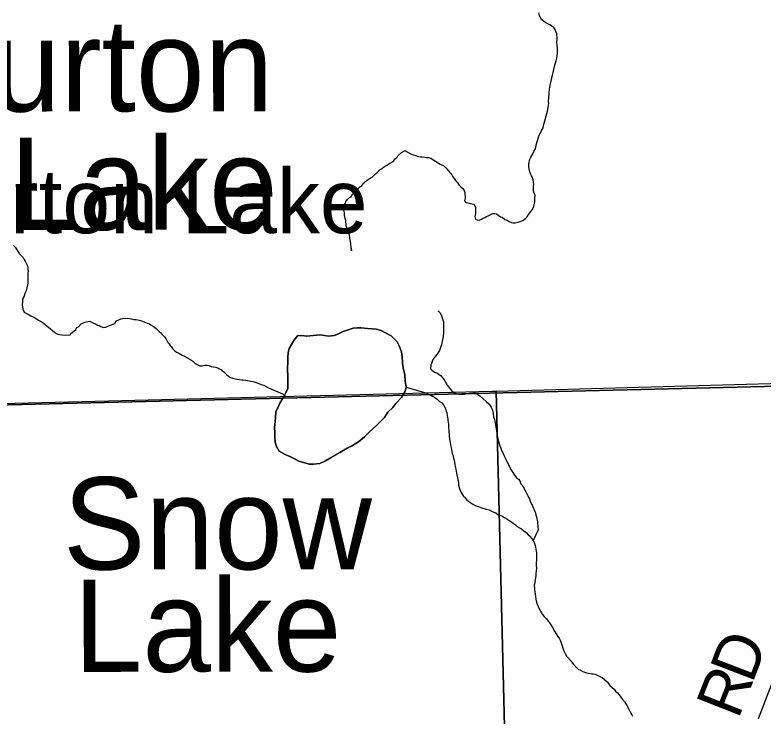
# Model space of a CAD drawing. Extents: x 10.6 to 44.6, y -2.6 to 23.4.
# Drawn here: x 15.619 to 16.54, y 20.49 to 21.353 of the extents above; entities that cross this region are included whole.
import ezdxf

# ---------------------------------------------------------------- set-up
doc = ezdxf.new("R2010")
doc.units = 0
for name, color, linetype in [('GM_X_County_Road', 7, 'Continuous'), ('GM_X_County_Road_Text', 7, 'Continuous'), ('GM_X_Minor_Lake', 7, 'Continuous'), ('GM_X_Minor_Lake_Text', 7, 'Continuous'), ('GM_X_Minor_River', 7, 'Continuous'), ('GM_X_Section', 7, 'Continuous'), ('GM_X_Township', 7, 'Continuous'), ('GM_X_Unincorporated_Text', 7, 'Continuous')]:
    doc.layers.add(name, color=color, linetype=linetype)

msp = doc.modelspace()

# ---------------------------------------------------------------- linework, layer by layer
at = {"layer": 'GM_X_County_Road'}
msp.add_lwpolyline([(16.56144, 20.55649), (16.53429, 20.48618)], dxfattribs=at)
at = {"layer": 'GM_X_Minor_Lake'}
for points in [[(15.94541, 20.87517), (15.95148, 20.88544), (15.95527, 20.89342), (15.95528, 20.90709), (15.9549, 20.91811), (15.95528, 20.9257), (15.95528, 20.9314), (15.95566, 20.93748), (15.9568, 20.94242), (15.96249, 20.9523), (15.96705, 20.958), (15.97236, 20.95839), (15.97843, 20.95763), (15.9864, 20.95841), (15.99437, 20.95955), (16.00044, 20.95842), (16.00575, 20.95767), (16.0122, 20.95843), (16.01751, 20.96072), (16.0232, 20.96338), (16.02813, 20.96529), (16.03572, 20.96758), (16.04066, 20.96796), (16.04559, 20.96797), (16.05318, 20.96722), (16.05887, 20.96684), (16.0638, 20.96647), (16.07025, 20.96458), (16.07556, 20.96193), (16.08239, 20.95814), (16.0896, 20.95055), (16.09225, 20.94562), (16.09529, 20.9384), (16.09605, 20.9327), (16.09642, 20.92435), (16.09718, 20.91865), (16.09908, 20.90992), (16.09983, 20.90232), (16.10097, 20.89473), (16.09983, 20.88979), (16.09528, 20.88219), (16.08807, 20.87496), (16.08427, 20.86964), (16.0782, 20.86394), (16.07403, 20.85747), (16.06454, 20.84797), (16.05505, 20.83884), (16.04974, 20.83352), (16.04215, 20.82743), (16.03342, 20.8221), (16.02811, 20.81982), (16.019, 20.81449), (16.00838, 20.8084), (16.00079, 20.80383), (15.99472, 20.80078), (15.98675, 20.80002), (15.98144, 20.80001), (15.97613, 20.80152), (15.96854, 20.80379), (15.96247, 20.80682), (15.95754, 20.80948), (15.95184, 20.81175), (15.94426, 20.81592), (15.94122, 20.82161), (15.9397, 20.82731), (15.93933, 20.83376), (15.93933, 20.83946), (15.93857, 20.84478), (15.94009, 20.85694), (15.94047, 20.86491), (15.94313, 20.87023), (15.94541, 20.87517)], [(16.09718, 20.91865), (16.09642, 20.92435), (16.09605, 20.9327), (16.09529, 20.9384), (16.09225, 20.94562), (16.0896, 20.95055), (16.08239, 20.95814), (16.07556, 20.96193), (16.07025, 20.96458), (16.0638, 20.96647), (16.05887, 20.96684), (16.05318, 20.96722), (16.04559, 20.96797), (16.04066, 20.96796), (16.03572, 20.96758), (16.02813, 20.96529), (16.0232, 20.96338), (16.01751, 20.96072), (16.0122, 20.95843), (16.00575, 20.95767), (16.00044, 20.95842), (15.99437, 20.95955), (15.9864, 20.95841), (15.97843, 20.95763), (15.97236, 20.95839), (15.96705, 20.958), (15.96249, 20.9523), (15.9568, 20.94242), (15.95566, 20.93748), (15.95528, 20.9314), (15.95528, 20.9257), (15.9549, 20.91811), (15.95528, 20.90709), (15.95527, 20.89342), (15.95148, 20.88544), (15.94541, 20.87517)], [(15.94541, 20.87517), (15.94313, 20.87023), (15.94047, 20.86491), (15.94009, 20.85694), (15.93857, 20.84478), (15.93933, 20.83946), (15.93933, 20.83376), (15.9397, 20.82731), (15.94122, 20.82161), (15.94426, 20.81592), (15.95184, 20.81175), (15.95754, 20.80948), (15.96247, 20.80682), (15.96854, 20.80379), (15.97613, 20.80152), (15.98144, 20.80001), (15.98675, 20.80002), (15.99472, 20.80078), (16.00079, 20.80383), (16.00838, 20.8084), (16.019, 20.81449), (16.02811, 20.81982), (16.03342, 20.8221), (16.04215, 20.82743), (16.04974, 20.83352), (16.05505, 20.83884), (16.06454, 20.84797), (16.07403, 20.85747), (16.0782, 20.86394), (16.08427, 20.86964), (16.08807, 20.87496), (16.09528, 20.88219), (16.09983, 20.88979), (16.10097, 20.89473), (16.09983, 20.90232), (16.09908, 20.90992), (16.09718, 20.91865)]]:
    msp.add_lwpolyline(points, dxfattribs=at)
at = {"layer": 'GM_X_Minor_River'}
for points in [[(16.21196, 21.10821), (16.21427, 21.10674), (16.21698, 21.1049), (16.21927, 21.10419), (16.22237, 21.1016), (16.22506, 21.10052), (16.22775, 21.09906), (16.23045, 21.0976), (16.23236, 21.09726), (16.23502, 21.09732), (16.23881, 21.09816), (16.24258, 21.09938), (16.24447, 21.10018), (16.24821, 21.10292), (16.25007, 21.10487), (16.25191, 21.10794), (16.2545, 21.11142), (16.25635, 21.11374), (16.25817, 21.11758), (16.25918, 21.12368), (16.25947, 21.12787), (16.25978, 21.13129), (16.25858, 21.13393), (16.25777, 21.13619), (16.25771, 21.13923), (16.25764, 21.14227), (16.25797, 21.14455), (16.25747, 21.15024), (16.25627, 21.15325), (16.25509, 21.15513), (16.25428, 21.15701), (16.25308, 21.16002), (16.25224, 21.16381), (16.25179, 21.16684), (16.25211, 21.16988), (16.25313, 21.1756), (16.25459, 21.1783), (16.25569, 21.18022), (16.25678, 21.18252), (16.25824, 21.18522), (16.26008, 21.1883), (16.26146, 21.19478), (16.26431, 21.20397), (16.26758, 21.21126), (16.26941, 21.21434), (16.27011, 21.21739), (16.27151, 21.22312), (16.27328, 21.22924), (16.27506, 21.23498), (16.27572, 21.23955), (16.27639, 21.24413), (16.27632, 21.24716), (16.27661, 21.25135), (16.27688, 21.25667), (16.27752, 21.26239), (16.27853, 21.26849), (16.27993, 21.27384), (16.28413, 21.29141), (16.28483, 21.29409), (16.28553, 21.29676), (16.28622, 21.30019), (16.28691, 21.30325), (16.28724, 21.30554), (16.28719, 21.3082), (16.28708, 21.31313), (16.28656, 21.31996), (16.28685, 21.32377), (16.28681, 21.32605), (16.28638, 21.32832), (16.28634, 21.33021), (16.28514, 21.33285), (16.28432, 21.33549), (16.28276, 21.33736), (16.28004, 21.33995), (16.27773, 21.34142), (16.27542, 21.34252), (16.27274, 21.3436), (16.27003, 21.34582), (16.2677, 21.34767), (16.26574, 21.35066), (16.26493, 21.35293), (16.2641, 21.35595)], [(16.03338, 21.06291), (16.03331, 21.06595), (16.03338, 21.06291), (16.03331, 21.06595), (16.0328, 21.07202), (16.03195, 21.07618), (16.03152, 21.07883), (16.03106, 21.08224), (16.03025, 21.0845), (16.02903, 21.08827), (16.02782, 21.09129), (16.02702, 21.09355), (16.02649, 21.10038), (16.02568, 21.10264), (16.02484, 21.10642), (16.02477, 21.10946), (16.02435, 21.11135), (16.02353, 21.11437), (16.02386, 21.11666), (16.02457, 21.11895), (16.02603, 21.12165), (16.02676, 21.12356), (16.02898, 21.12627), (16.03121, 21.1286), (16.03309, 21.12978), (16.03493, 21.13248), (16.03679, 21.13442), (16.03866, 21.13636), (16.04126, 21.13908), (16.04349, 21.1414), (16.04611, 21.14336), (16.04872, 21.14608), (16.05282, 21.14997), (16.05657, 21.15233), (16.05883, 21.15352), (16.0633, 21.1578), (16.06517, 21.15936), (16.06703, 21.1613), (16.0689, 21.16286), (16.07115, 21.16443), (16.07302, 21.16599), (16.07527, 21.16756), (16.07715, 21.16835), (16.08053, 21.17033), (16.08466, 21.17308), (16.08763, 21.17656), (16.08988, 21.17813), (16.0906, 21.18005), (16.09508, 21.18395), (16.09959, 21.18632), (16.10191, 21.18485), (16.10499, 21.18302), (16.10729, 21.18193), (16.10959, 21.18122), (16.11151, 21.1805), (16.11457, 21.17943), (16.11839, 21.17875), (16.12068, 21.17842), (16.12373, 21.17811), (16.12602, 21.17778), (16.1283, 21.17783), (16.13136, 21.17713), (16.14293, 21.16979), (16.14716, 21.1676), (16.14988, 21.165), (16.15262, 21.16164), (16.15573, 21.15829), (16.15691, 21.15641), (16.15848, 21.15417), (16.16005, 21.15192), (16.16163, 21.1493), (16.16357, 21.14744), (16.16593, 21.14369), (16.16826, 21.14184), (16.17059, 21.13961), (16.17216, 21.13699), (16.17297, 21.13472), (16.17351, 21.12752), (16.17281, 21.12446), (16.17438, 21.12221), (16.17667, 21.12189), (16.17973, 21.12119), (16.18164, 21.12085), (16.18432, 21.12015), (16.1855, 21.11828), (16.18631, 21.11602), (16.18635, 21.11412), (16.18609, 21.10841), (16.1854, 21.10498), (16.18623, 21.10195), (16.18815, 21.10086), (16.19082, 21.10053), (16.19271, 21.10134), (16.19496, 21.10252), (16.1976, 21.10372), (16.19985, 21.10529), (16.20174, 21.10609), (16.20513, 21.10769), (16.20776, 21.10888), (16.21004, 21.10893), (16.21196, 21.10821)], [(15.61745, 21.06943), (15.61941, 21.0672), (15.62452, 21.05933), (15.62724, 21.05673), (15.62919, 21.05449), (15.63038, 21.05224), (15.63156, 21.04998), (15.63315, 21.04698), (15.63435, 21.04434), (15.63478, 21.04207), (15.63483, 21.03979), (15.63525, 21.0379), (15.63492, 21.03524), (15.63498, 21.03258), (15.63505, 21.02916), (15.6351, 21.02688), (15.63476, 21.02497)], [(15.63476, 21.02497), (15.6348, 21.02307), (15.63447, 21.02078), (15.63378, 21.01735), (15.63273, 21.01353), (15.63127, 21.01046), (15.63057, 21.0074), (15.62947, 21.00548), (15.62838, 21.00317), (15.62845, 21.00013), (15.62815, 20.99633), (15.62821, 20.99329), (15.62905, 20.98951), (15.63062, 20.98726), (15.63332, 20.9858), (15.6364, 20.98397), (15.6387, 20.98288), (15.6414, 20.98142), (15.64447, 20.97997), (15.64795, 20.97738), (15.65257, 20.97482), (15.65683, 20.97149), (15.66031, 20.96891), (15.66728, 20.96298), (15.66921, 20.9615), (15.67191, 20.96004), (15.6742, 20.95971), (15.67687, 20.95939), (15.68182, 20.95912), (15.68562, 20.9592), (15.68752, 20.95924), (15.68786, 20.96115), (15.69161, 20.96389), (15.69385, 20.96584), (15.69531, 20.96853), (15.6972, 20.96933), (15.70055, 20.97283), (15.70243, 20.97363), (15.70696, 20.97525), (15.71113, 20.9761), (15.71574, 20.97392), (15.71842, 20.97284), (15.72074, 20.97137), (15.72266, 20.97065), (15.72496, 20.96956), (15.72803, 20.96849), (15.73106, 20.96893), (15.73332, 20.97012), (15.74011, 20.97255), (15.74237, 20.97374), (15.74346, 20.97604), (15.74948, 20.97921), (15.75213, 20.97965), (15.75708, 20.97976), (15.76013, 20.97945), (15.7628, 20.97912), (15.76548, 20.97842), (15.76852, 20.97811), (15.77196, 20.97742), (15.77502, 20.97673), (15.7781, 20.97527), (15.78193, 20.97384), (15.78462, 20.97276), (15.78654, 20.97166), (15.78924, 20.9702), (15.7931, 20.96724), (15.79466, 20.96538), (15.79661, 20.96352), (15.79893, 20.96167), (15.80049, 20.9598), (15.80322, 20.95682), (15.80478, 20.95496), (15.80598, 20.95232), (15.80755, 20.95008), (15.80911, 20.94821), (15.81029, 20.94634), (15.81185, 20.94447), (15.81303, 20.9426), (15.81614, 20.93963), (15.81807, 20.93815), (15.82077, 20.93669), (15.82307, 20.93559), (15.82499, 20.9345), (15.82692, 20.9334), (15.82999, 20.93195), (15.83577, 20.92865), (15.83809, 20.9268), (15.84119, 20.92421), (15.84427, 20.92238), (15.84658, 20.92129), (15.84962, 20.92136), (15.85342, 20.92182), (15.8557, 20.92187), (15.85799, 20.92154), (15.86067, 20.92046), (15.86373, 20.91976), (15.8664, 20.91944), (15.86832, 20.91872), (15.87101, 20.91764), (15.87332, 20.91617), (15.87642, 20.91358)], [(16.13989, 20.98894), (16.14072, 20.98849), (16.14266, 20.98663), (16.14426, 20.98287), (16.14508, 20.98023), (16.14589, 20.97796), (16.14671, 20.97532), (16.14691, 20.96583), (16.14701, 20.96127), (16.14633, 20.95745), (16.14565, 20.95364), (16.14532, 20.95135), (16.14461, 20.94906), (16.14427, 20.94715), (16.1432, 20.94371), (16.14175, 20.94026), (16.13955, 20.93641), (16.13734, 20.93332), (16.13548, 20.931), (16.13362, 20.92906), (16.13221, 20.92409), (16.13111, 20.92179), (16.13082, 20.9176), (16.13238, 20.91574), (16.13586, 20.91353), (16.13931, 20.91209), (16.14163, 20.91062), (16.14356, 20.90914), (16.14513, 20.90689), (16.14747, 20.9039), (16.14944, 20.90091), (16.15142, 20.89715), (16.15337, 20.89491), (16.15455, 20.89304), (16.15688, 20.89081), (16.15921, 20.88858), (16.16114, 20.88748), (16.16534, 20.88643), (16.16991, 20.88615), (16.1722, 20.8862), (16.17599, 20.88705), (16.17902, 20.88749), (16.18281, 20.88795), (16.18547, 20.88801), (16.18739, 20.88729), (16.19164, 20.88434), (16.19552, 20.88063), (16.1994, 20.8773), (16.2025, 20.87432), (16.20445, 20.87246), (16.20563, 20.87021), (16.20724, 20.86645), (16.20807, 20.86305), (16.20856, 20.85811), (16.20976, 20.8551), (16.2102, 20.85245), (16.21103, 20.84905), (16.21149, 20.84564), (16.21153, 20.84336), (16.21197, 20.84071), (16.21241, 20.83806), (16.21285, 20.83503), (16.21493, 20.82672), (16.21616, 20.82256), (16.21737, 20.81955), (16.21819, 20.81691), (16.21938, 20.81465), (16.22057, 20.81202), (16.22217, 20.80863), (16.22375, 20.80563), (16.22573, 20.80225), (16.22733, 20.79849), (16.2301, 20.79323), (16.23365, 20.7876), (16.23679, 20.78311), (16.2391, 20.78164), (16.24067, 20.7794), (16.24227, 20.77601), (16.24383, 20.77415), (16.24502, 20.77189), (16.2462, 20.77002), (16.247, 20.76813), (16.24819, 20.76588), (16.24978, 20.7625), (16.25137, 20.75949), (16.25256, 20.75724), (16.25375, 20.7546), (16.25455, 20.75272), (16.25535, 20.75084), (16.25655, 20.74858), (16.25735, 20.74632), (16.25855, 20.74369), (16.25935, 20.74181), (16.26015, 20.73992), (16.26059, 20.73727), (16.2614, 20.73501), (16.26183, 20.73274), (16.26225, 20.73085)], [(15.87642, 20.91358), (15.87952, 20.91061), (15.88262, 20.90802), (15.88455, 20.90692), (15.88685, 20.90583), (15.89029, 20.90514), (15.89258, 20.90481), (15.89525, 20.90449), (15.89831, 20.9038), (15.90021, 20.90384), (15.90326, 20.90352), (15.90555, 20.90319), (15.91166, 20.90181), (15.91358, 20.90147), (15.91625, 20.90077), (15.91933, 20.89931), (15.92239, 20.89824), (15.92546, 20.89717), (15.92853, 20.89571), (15.93123, 20.89425), (15.95148, 20.88544)], [(16.10097, 20.89473), (16.12652, 20.88749), (16.12884, 20.88602), (16.13114, 20.88493), (16.13345, 20.88384), (16.13615, 20.882), (16.13885, 20.88016), (16.14196, 20.87718), (16.14465, 20.87572), (16.14699, 20.87311), (16.14858, 20.87011), (16.14978, 20.86709), (16.1502, 20.8652), (16.151, 20.86332), (16.15146, 20.85991), (16.15189, 20.85764), (16.15231, 20.85575), (16.15236, 20.85347), (16.1524, 20.85157), (16.15283, 20.8493), (16.15287, 20.84702), (16.15292, 20.84474), (16.15335, 20.84247), (16.15341, 20.83981), (16.15384, 20.83716), (16.15391, 20.83413), (16.15436, 20.8311), (16.15479, 20.82845), (16.15521, 20.82656), (16.15564, 20.82428), (16.1557, 20.82163), (16.15652, 20.8186), (16.15697, 20.81557), (16.1574, 20.8133), (16.1582, 20.81142), (16.15862, 20.80953), (16.15905, 20.80726), (16.15986, 20.805), (16.16029, 20.80235), (16.16073, 20.7997), (16.16117, 20.79705), (16.16199, 20.79402), (16.16243, 20.79137), (16.16286, 20.7891), (16.16455, 20.78116), (16.16497, 20.77927), (16.16539, 20.77738), (16.16546, 20.77434), (16.16628, 20.77132), (16.1671, 20.76868), (16.16869, 20.76529), (16.16988, 20.76304), (16.17106, 20.76116), (16.17263, 20.7593), (16.17535, 20.75631), (16.17806, 20.75409), (16.18039, 20.75225), (16.18308, 20.75078), (16.18577, 20.74932), (16.18961, 20.74789), (16.19421, 20.74609), (16.19919, 20.74467), (16.20301, 20.74362), (16.20609, 20.74217), (16.20877, 20.74109), (16.21146, 20.74), (16.21378, 20.73815), (16.21762, 20.73672), (16.21992, 20.73563), (16.22185, 20.73453), (16.22493, 20.7327), (16.22725, 20.73085), (16.22995, 20.72939), (16.23265, 20.72755), (16.23536, 20.72532), (16.23769, 20.72309), (16.24038, 20.72163), (16.24308, 20.72017), (16.24579, 20.71795), (16.2485, 20.71573), (16.2516, 20.71276), (16.25354, 20.71128), (16.25511, 20.70866), (16.25745, 20.70605), (16.25865, 20.70341), (16.25986, 20.70002), (16.26029, 20.69775), (16.26072, 20.69548), (16.26078, 20.69282), (16.2612, 20.69093), (16.2614, 20.68143), (16.26108, 20.67877), (16.26114, 20.67573), (16.26123, 20.67193), (16.26092, 20.6685), (16.2606, 20.66545)], [(16.26225, 20.73085), (16.26267, 20.72896), (16.26271, 20.72706), (16.26315, 20.72441), (16.26319, 20.72251), (16.26326, 20.71909), (16.25745, 20.70605)], [(16.2606, 20.66545), (16.26066, 20.6628), (16.26034, 20.66013), (16.25963, 20.65745), (16.25929, 20.65555), (16.25933, 20.65365), (16.25863, 20.65097), (16.25871, 20.64717), (16.25876, 20.6449), (16.25919, 20.64263), (16.25963, 20.63997), (16.26007, 20.63695), (16.26052, 20.63353), (16.26136, 20.63013), (16.26217, 20.62749), (16.26337, 20.62486), (16.26418, 20.62259), (16.26536, 20.62072), (16.26616, 20.61884), (16.26734, 20.61696), (16.26852, 20.61509), (16.27086, 20.61248), (16.27359, 20.6095), (16.27594, 20.60651), (16.2775, 20.60464), (16.27907, 20.60202), (16.28104, 20.59902), (16.28342, 20.59451), (16.28577, 20.59115), (16.28775, 20.58777), (16.28932, 20.58552), (16.29051, 20.58327), (16.29131, 20.58101), (16.29213, 20.57874), (16.29294, 20.5761), (16.29376, 20.57346), (16.29458, 20.57082), (16.29577, 20.56856), (16.29696, 20.56593), (16.29892, 20.56331), (16.3036, 20.55771), (16.30556, 20.5551), (16.30751, 20.55286), (16.30985, 20.55025), (16.31296, 20.54728), (16.31488, 20.54656), (16.31757, 20.5451), (16.32064, 20.54365), (16.32294, 20.54294), (16.32523, 20.5426), (16.32752, 20.54227), (16.32943, 20.54194), (16.33134, 20.5416), (16.33363, 20.54127), (16.3367, 20.53981), (16.34016, 20.53799), (16.34208, 20.53727), (16.34518, 20.53468), (16.34829, 20.53171), (16.34985, 20.52984), (16.35181, 20.52722), (16.35452, 20.525), (16.35685, 20.52277), (16.3588, 20.52054), (16.36113, 20.51831), (16.36308, 20.51607), (16.36542, 20.51308), (16.36739, 20.51008), (16.36973, 20.50747), (16.3713, 20.50485), (16.37288, 20.50222), (16.37446, 20.4996), (16.37644, 20.49584), (16.37764, 20.49321), (16.37882, 20.49133), (16.37962, 20.48945)]]:
    msp.add_lwpolyline(points, dxfattribs=at)
at = {"layer": 'GM_X_Section'}
for points in [[(17.17051, 20.91202), (17.1955, 19.83846), (16.23849, 19.81579), (16.21154, 20.88991), (16.6813, 20.903), (17.15214, 20.91165)], [(16.21154, 20.88991), (16.23849, 19.81579), (15.27309, 19.80416), (15.27236, 20.06854), (15.25854, 20.86618), (15.73438, 20.87807), (16.20669, 20.88983)]]:
    msp.add_lwpolyline(points, close=True, dxfattribs=at)
at = {"layer": 'GM_X_Township'}
for points in [[(15.23634, 22.32669), (15.23748, 22.26398), (15.23889, 21.94438), (15.24934, 21.22179), (15.25138, 21.08076), (15.25451, 20.86458), (16.64382, 20.89834), (17.62302, 20.91969), (18.6416, 20.92773), (19.65809, 20.9527), (20.00331, 20.95729)], [(20.00331, 20.95729), (19.65809, 20.9527), (18.6416, 20.92773), (17.62302, 20.91969), (16.64382, 20.89834), (15.25451, 20.86458), (15.25866, 20.59578), (15.26846, 20.05099), (15.2709, 19.56461)]]:
    msp.add_lwpolyline(points, dxfattribs=at)

# ---------------------------------------------------------------- texts
at = {"layer": 'GM_X_County_Road_Text'}
for s, rotation, p in [('D', 69.07417, (16.52698, 20.52875)), ('R', 68.51022, (16.50966, 20.48476))]:
    msp.add_text(s, height=0.05682, rotation=rotation, dxfattribs=at).set_placement(p)
at = {"layer": 'GM_X_Minor_Lake_Text'}
for s, rotation, p in [('Burton', 0.06697, (15.48925, 21.23427)), ('Lake', 0.06752, (15.61303, 21.08858)), ('Snow', 0.06818, (15.67839, 20.6702)), ('Lake', 0.06863, (15.69147, 20.54415))]:
    msp.add_text(s, height=0.113704, rotation=rotation, dxfattribs=at).set_placement(p)
at = {"layer": 'GM_X_Unincorporated_Text'}
msp.add_text('Burton Lake', height=0.0789773, rotation=0.00001, dxfattribs=at).set_placement((15.48384, 21.08451))

doc.saveas('drawing.dxf')
